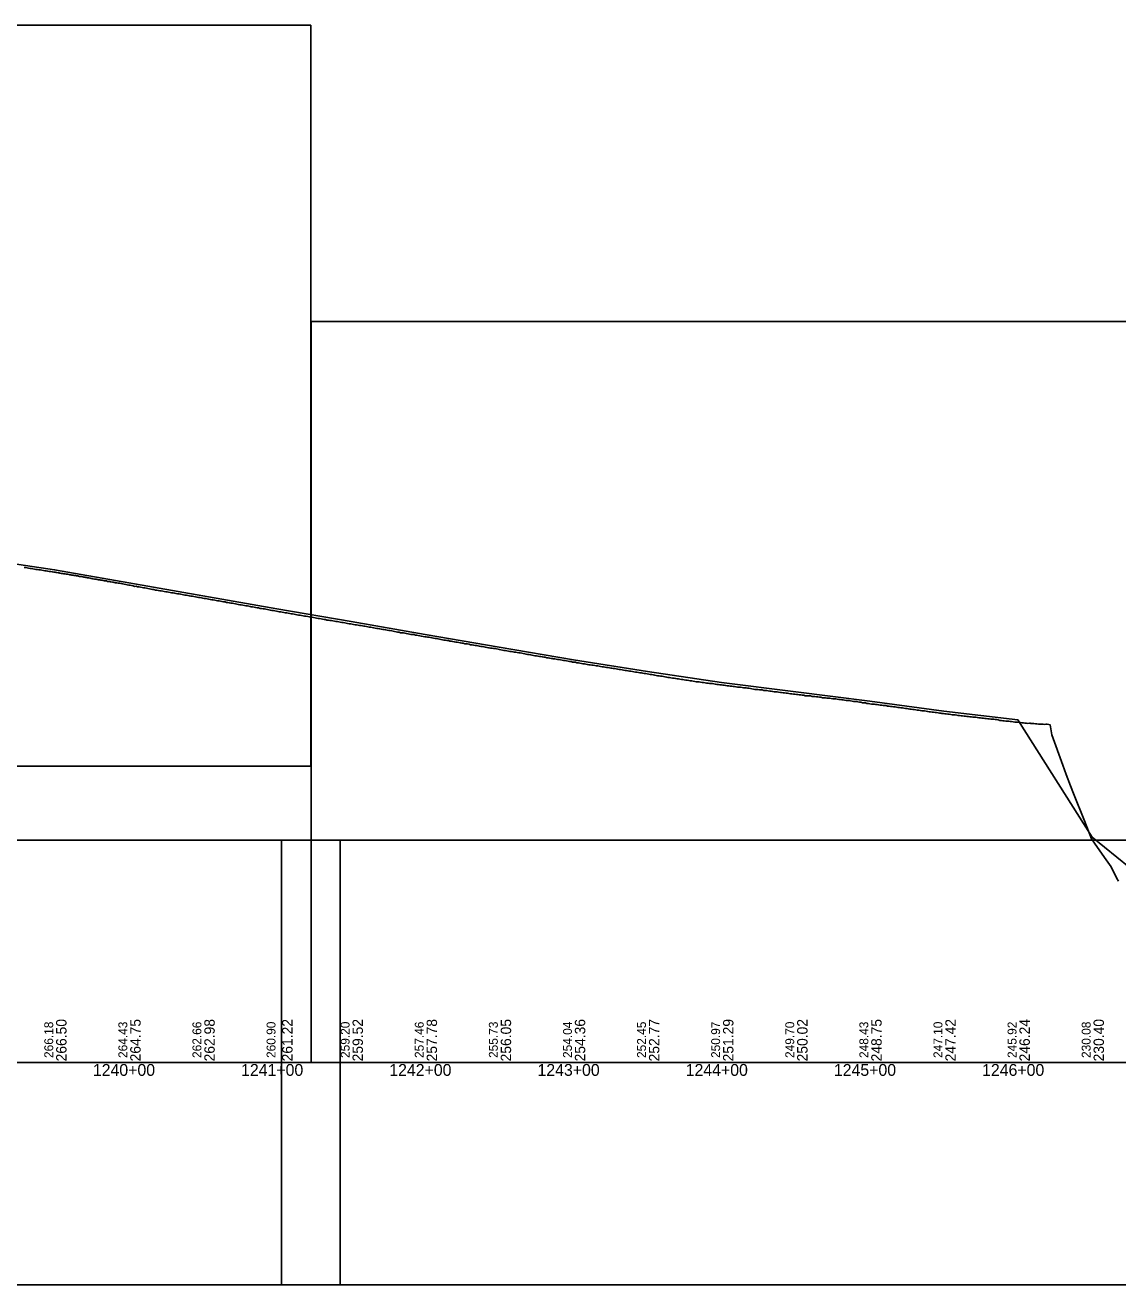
# Model space of a CAD drawing. Extents: x -3627 to 47473, y 2850 to 4350.
# Drawn here: x 11307 to 12045, y 2850 to 3700 of the extents above; entities that cross this region are included whole.
import ezdxf

# ---------------------------------------------------------------- set-up
doc = ezdxf.new("R2010")
doc.units = 0
for name, color, linetype in [('RD_DDB_Profile_EX', 7, 'Continuous'), ('RD_DDB_Profile_PR', 7, 'Continuous'), ('RD_DDB_StaTX', 7, 'Continuous'), ('RD_DDB_StripGrade', 7, 'Continuous'), ('RD_GPK_Profile_Cell', 7, 'Continuous'), ('RD_SHT_ShtClip', 7, 'Continuous')]:
    doc.layers.add(name, color=color, linetype=linetype)

msp = doc.modelspace()

# ---------------------------------------------------------------- linework, layer by layer
at = {"layer": 'RD_DDB_Profile_EX'}
for points in [[(11306.702497, 3334.127615), (11307.703786, 3333.95557), (11308.704824, 3333.8417), (11309.698455, 3333.641885), (11310.701927, 3333.44198), (11311.700801, 3333.30623), (11312.700777, 3333.06418), (11313.701759, 3333.02838), (11314.703124, 3332.79284), (11315.697828, 3332.67114), (11316.697823, 3332.52178), (11317.70129, 3332.421955), (11318.70017, 3332.23674), (11319.70019, 3332.09376), (11320.701094, 3331.908395), (11321.70111, 3331.79419), (11322.697231, 3331.55856), (11323.697271, 3331.42955), (11324.700734, 3331.329625), (11325.699621, 3331.194645), (11326.699688, 3330.96007), (11327.700509, 3330.860125), (11328.398137, 3330.755555), (11328.727924, 3330.695325), (11329.7239, 3330.44505), (11330.421897, 3330.340395), (11330.724297, 3330.234955), (11331.72652, 3330.080035), (11332.424528, 3329.975325), (11333.018039, 3329.940345), (11333.319138, 3329.880155), (11334.016473, 3329.775635), (11334.319858, 3329.73021), (11335.314757, 3329.53994), (11336.013378, 3329.434935), (11336.314595, 3329.45), (11337.015833, 3329.24021), (11337.316486, 3329.19517), (11338.014271, 3329.125525), (11338.316319, 3329.08025), (11339.016724, 3328.94046), (11339.319099, 3328.88011), (11340.011169, 3328.775205), (11340.311938, 3328.7), (11341.310819, 3328.56999), (11342.009598, 3328.43011), (11342.310648, 3328.415075)], [(11342.310648, 3328.415075), (11343.012061, 3328.310105), (11343.312543, 3328.219905), (11344.004769, 3328.080065), (11344.306261, 3328.06501), (11345.308154, 3327.935015), (11346.007394, 3327.76013), (11346.307993, 3327.7), (11347.009857, 3327.59501), (11347.309885, 3327.55), (11348.008282, 3327.4103), (11348.30972, 3327.365095), (11349.005027, 3327.259925), (11349.305482, 3327.17008), (11350.005187, 3327.06501), (11350.305332, 3327.03497), (11351.307221, 3326.854995), (11352.00608, 3326.54031), (11352.307066, 3326.525365), (11353.004508, 3326.45586), (11353.307794, 3326.35), (11354.302664, 3326.219985), (11355.001418, 3326.15), (11355.302523, 3326.11984), (11356.003876, 3325.945085), (11356.304405, 3325.91505), (11357.002307, 3325.7057), (11357.304261, 3325.660485), (11357.999044, 3325.62503), (11358.299989, 3325.594955), (11358.99921, 3325.52517), (11359.299859, 3325.465055), (11360.001669, 3325.36002), (11360.301738, 3325.269945), (11361.000104, 3325.130155), (11361.301604, 3325.0849), (11362.002562, 3325.01505), (11362.303483, 3324.96986), (11362.995274, 3324.690325), (11363.297188, 3324.66013), (11364.299064, 3324.49501), (11364.997899, 3324.42527), (11365.29894, 3324.365075), (11366.297795, 3324.21502), (11366.990607, 3324.11001), (11367.290629, 3324.034975), (11367.993075, 3323.82487), (11368.29337, 3323.76495), (11369.193142, 3323.684985), (11370.194703, 3323.514875), (11371.192429, 3323.385125), (11372.189034, 3323.179475), (11373.186775, 3323.029475), (11374.187253, 3322.8), (11375.28425, 3322.59362), (11376.282005, 3322.320915), (11377.282798, 3322.17889), (11378.276693, 3322.043225), (11379.277501, 3321.828625), (11380.275278, 3321.664315), (11381.277354, 3321.320895), (11382.277735, 3321.36421), (11383.272049, 3321.106195), (11384.269851, 3320.928105), (11385.273311, 3320.763985), (11386.272322, 3320.6), (11387.266653, 3320.427585), (11388.267001, 3320.277645), (11389.267946, 3320.07746), (11390.265778, 3319.80494), (11391.263786, 3319.740695), (11392.261634, 3319.53643), (11393.259481, 3319.204315), (11394.26049, 3319.176975), (11395.260802, 3318.85407), (11396.256321, 3318.75), (11397.254191, 3318.636665), (11398.257666, 3318.40307), (11399.255541, 3318.25), (11400.249921, 3318.136875), (11401.250201, 3317.88946), (11402.252432, 3317.678185), (11403.250329, 3317.56304), (11404.253817, 3317.4), (11405.244981, 3317.22584), (11406.246128, 3317.024335), (11407.245164, 3316.9), (11408.24866, 3316.8), (11409.239809, 3316.50076), (11410.241007, 3316.32521), (11411.241232, 3316.187905), (11412.270572, 3316.06251), (11413.262888, 3315.82503), (11414.263934, 3315.537), (11415.264213, 3315.47492), (11416.265277, 3315.362375), (11417.265549, 3315.174815), (11418.259658, 3314.89904), (11419.314207, 3314.79913), (11420.305281, 3314.61223), (11421.307684, 3314.398795)], [(11421.307684, 3314.398795), (11422.305665, 3314.236635), (11423.309122, 3314.09859), (11424.300189, 3313.84839), (11425.30364, 3313.712035), (11426.301637, 3313.6), (11427.305094, 3313.311985), (11428.303095, 3313.161995), (11429.29858, 3313.023805), (11430.296589, 3312.861915), (11431.300052, 3312.597405), (11432.298064, 3312.485595), (11433.294557, 3312.28522), (11434.29473, 3312.161775), (11435.296045, 3311.985075), (11436.29621, 3311.785175), (11437.28954, 3311.56161), (11438.289698, 3311.461645), (11439.291045, 3311.31156), (11440.291196, 3311.034785), (11441.285537, 3310.911455), (11442.285681, 3310.77297), (11443.287058, 3310.538595), (11444.287195, 3310.32288), (11445.287601, 3310.145545), (11446.280691, 3310.034075), (11447.282098, 3309.91128), (11448.282221, 3309.722625), (11449.280283, 3309.538675), (11450.276694, 3309.283615), (11451.274767, 3308.98976), (11452.278239, 3308.92232), (11453.275344, 3308.7612), (11454.271744, 3308.62216), (11455.382957, 3308.45), (11456.385126, 3308.261085), (11457.384879, 3308.144265), (11458.38774, 3307.922405), (11459.158416, 3307.65), (11459.929866, 3307.561015), (11460.932525, 3307.46098), (11461.931425, 3307.28896), (11462.927222, 3307.15), (11463.930938, 3306.87177), (11464.929843, 3306.72811), (11465.925625, 3306.471695), (11466.928297, 3306.35), (11467.928245, 3306.260845), (11468.924011, 3306.042995), (11469.924807, 3305.82861), (11470.916795, 3305.689305), (11471.919483, 3305.471315), (11472.9232, 3305.181785), (11473.915171, 3305.08178), (11474.917865, 3304.95), (11475.920567, 3304.73948), (11476.912524, 3304.6), (11477.916231, 3304.410455), (11478.911961, 3304.14142), (11479.910879, 3304.08125), (11480.913588, 3303.91038), (11481.909313, 3303.760275), (11482.909217, 3303.52937), (11483.911933, 3303.410275), (11484.90585, 3303.189845), (11485.904761, 3303.06022), (11486.90847, 3302.840625), (11487.904179, 3302.75), (11488.903095, 3302.55), (11489.898791, 3302.3), (11490.901538, 3302.079915), (11491.901412, 3301.93999), (11492.897091, 3301.8), (11493.899845, 3301.690135), (11494.898765, 3301.54007), (11495.89444, 3301.30982), (11496.898134, 3301.15), (11498.084495, 3300.99025), (11499.082949, 3300.790225), (11500.083358, 3300.55), (11501.083772, 3300.44015), (11502.076535, 3300.261185), (11503.076945, 3300.04026), (11504.074824, 3299.76958), (11505.075233, 3299.74017), (11506.076064, 3299.54025), (11507.076465, 3299.430425), (11508.074909, 3299.23038), (11509.075311, 3299.030305), (11510.078107, 3298.8913), (11511.07596, 3298.54017), (11512.076358, 3298.470395), (11513.074786, 3298.3), (11514.077599, 3298.240175), (11515.068024, 3298.07065), (11516.068418, 3297.93036), (11517.068817, 3297.64014), (11518.069075, 3297.53039), (11519.069465, 3297.370475), (11520.067894, 3297.130275), (11521.068284, 3297.0302)], [(11521.068284, 3297.0302), (11522.069147, 3296.880355), (11523.069531, 3296.7), (11524.069918, 3296.44062), (11524.870833, 3296.360215), (11526.070565, 3296.11976), (11527.068981, 3296.030195), (11528.061393, 3295.85), (11528.86275, 3295.649615), (11530.062649, 3295.440165), (11531.063029, 3295.280255), (11532.061447, 3295.180215), (11533.061219, 3294.95995), (11534.0621, 3294.83025), (11535.062473, 3294.65), (11535.863082, 3294.52988), (11536.652242, 3294.36991), (11537.652092, 3294.15), (11538.655829, 3293.91986), (11539.653933, 3293.79005), (11540.652812, 3293.67002), (11541.654813, 3293.529805), (11542.647632, 3293.279725), (11543.645738, 3293.1), (11544.645586, 3292.95), (11545.649322, 3292.8), (11546.647428, 3292.579775), (11547.725313, 3292.45997), (11548.728588, 3292.21982), (11549.728712, 3292.11989), (11550.72806, 3291.910005), (11551.726314, 3291.729955), (11552.728804, 3291.60999), (11553.728931, 3291.429955), (11554.728272, 3291.23992), (11555.719036, 3291.03996), (11556.721522, 3290.82999), (11557.721653, 3290.66988), (11558.719903, 3290.5), (11559.722391, 3290.320045), (11560.72252, 3290.06035), (11561.721859, 3289.980345), (11562.720098, 3289.9), (11563.722584, 3289.6404), (11564.722715, 3289.4), (11565.722048, 3289.31019), (11566.720278, 3289.09084), (11567.723568, 3288.90076), (11568.715444, 3288.81015), (11569.713679, 3288.75), (11570.716163, 3288.480405), (11571.716296, 3288.340675), (11572.715628, 3288.1409), (11573.713853, 3287.990975), (11574.716335, 3287.78979), (11576.009865, 3287.46152), (11577.002754, 3287.35114), (11578.003685, 3287.230535), (11579.007399, 3287.070245), (11579.999286, 3286.93036), (11581.001219, 3286.78014), (11582.000125, 3286.57021), (11583.003839, 3286.38014), (11583.999548, 3286.239815), (11584.997659, 3286.12992), (11586.001373, 3285.86983), (11587.00028, 3285.65997), (11587.996928, 3285.56971), (11588.9941, 3285.24949), (11589.997814, 3285.08936), (11590.993506, 3284.97924), (11591.991634, 3284.81953), (11592.994412, 3284.688925), (11593.994254, 3284.429295), (11594.990866, 3284.3), (11595.991959, 3284.0096), (11596.991788, 3283.959635), (11597.987464, 3283.728615), (11598.987293, 3283.6), (11599.988407, 3283.46905), (11600.999406, 3283.3), (11601.993282, 3282.997275), (11602.996052, 3282.928255), (11603.995902, 3282.640545), (11604.998672, 3282.60942), (11605.99131, 3282.487575), (11606.99408, 3282.28743), (11607.995203, 3281.83723), (11608.987813, 3281.78713), (11609.990596, 3281.686985), (11610.990433, 3281.514975), (11611.993217, 3281.436985), (11612.984945, 3281.155455), (11613.988588, 3280.91837), (11614.989754, 3280.727405), (11615.989577, 3280.62751), (11616.985112, 3280.55), (11617.984083, 3280.27739), (11618.987732, 3280.14093), (11619.98325, 3279.92692), (11620.491182, 3279.8138)], [(11620.491182, 3279.8138), (11621.485517, 3279.705245), (11622.485183, 3279.522975), (11623.485443, 3279.41809), (11624.487798, 3279.29099), (11625.488058, 3279.1), (11626.480621, 3278.891065), (11627.480287, 3278.62697), (11628.483236, 3278.40893), (11629.482902, 3278.28202), (11630.48585, 3278.05893), (11631.477474, 3278), (11632.475392, 3277.767945), (11633.47834, 3277.658915), (11634.478006, 3277.45), (11635.480954, 3277.3), (11636.48062, 3277.15897), (11637.474933, 3276.976615), (11638.473444, 3276.8), (11639.475811, 3276.65886), (11640.476058, 3276.508895), (11641.478425, 3276.35), (11642.470035, 3276.14688), (11643.470289, 3275.9), (11644.470916, 3275.73536), (11645.471163, 3275.541125), (11646.425702, 3275.4), (11647.424086, 3275.258845), (11648.418672, 3275.126075), (11649.417069, 3274.873855), (11650.420344, 3274.682685), (11651.419426, 3274.55), (11652.421093, 3274.441405), (11653.411748, 3274.28289), (11654.410832, 3274.05856), (11655.414116, 3273.91701), (11656.413202, 3273.71702), (11657.414909, 3273.60844), (11658.405557, 3273.458405), (11659.407955, 3273.10832), (11660.407939, 3273.05), (11661.409684, 3272.85829), (11662.408773, 3272.68341), (11663.241396, 3272.55834), (11663.748903, 3272.508235), (11664.742062, 3272.35), (11665.744382, 3272.174375), (11666.742619, 3271.94185), (11667.745755, 3271.858065), (11668.740776, 3271.71588), (11669.740418, 3271.515955), (11670.743565, 3271.342105), (11671.741818, 3271.2), (11672.737609, 3270.97666), (11673.735871, 3270.842195), (11674.739634, 3270.66899), (11675.742809, 3270.561645), (11676.733682, 3270.254165), (11677.73612, 3270.131825), (11678.735139, 3270.05449), (11679.738909, 3269.76987), (11680.730504, 3269.675155), (11681.732966, 3269.39805), (11682.73545, 3269.333775), (11683.728297, 3269.09875), (11684.730786, 3268.984665), (11685.729083, 3268.86985), (11686.732307, 3268.699535), (11687.723139, 3268.442325), (11688.727609, 3268.26466), (11689.730143, 3268.1295), (11690.728453, 3268.079225), (11691.724199, 3267.951385), (11692.722517, 3267.74422), (11693.726294, 3267.63079), (11694.725297, 3267.523725), (11695.735083, 3267.268225), (11696.738749, 3267.0756), (11697.737703, 3266.96823), (11698.741369, 3266.73913), (11699.73146, 3266.652765), (11700.735125, 3266.52991), (11701.73408, 3266.336505), (11702.730059, 3266.1), (11703.212794, 3266.086715), (11704.215852, 3265.9), (11705.215409, 3265.830075), (11706.210078, 3265.65427), (11707.208375, 3265.517125), (11708.211433, 3265.273905), (11709.21145, 3265.123755), (11710.205647, 3264.93707), (11711.208694, 3264.743585), (11712.207014, 3264.587085), (11713.201647, 3264.430955), (11714.201215, 3264.2372), (11715.204263, 3264.17461), (11716.202595, 3264.02444), (11717.197216, 3263.831155), (11718.199829, 3263.587515), (11719.199831, 3263.48744)], [(11719.199831, 3263.48744), (11720.192787, 3263.33765), (11721.192784, 3263.18136), (11722.195402, 3262.969125), (11723.195399, 3262.887575), (11724.18836, 3262.64389), (11725.191411, 3262.5), (11726.190975, 3262.44389), (11727.194026, 3262.251545), (11728.183933, 3262.069795), (11729.186984, 3261.88203), (11730.186548, 3261.78792), (11731.181087, 3261.626275), (11732.18372, 3261.376435), (11733.182557, 3261.18223), (11734.185608, 3261.026515), (11735.176647, 3260.88241), (11736.179689, 3260.738375), (11737.181215, 3260.621175), (11738.172633, 3260.421275), (11739.175279, 3260.215765), (11740.175249, 3260.071275), (11741.176793, 3259.838605), (11742.168193, 3259.72729), (11743.170844, 3259.627445), (11744.257976, 3259.45517), (11745.25965, 3259.311105), (11746.254321, 3259.17822), (11747.25707, 3258.983785), (11748.251699, 3258.83412), (11749.244917, 3258.67926), (11750.186584, 3258.54486), (11751.182493, 3258.37989), (11752.185762, 3258.24003), (11753.181158, 3258.1), (11754.189346, 3257.995265), (11755.184726, 3257.84537), (11756.188035, 3257.627055), (11757.183844, 3257.47763), (11758.179187, 3257.336895), (11759.182516, 3257.195675), (11760.17785, 3256.995785), (11761.181601, 3256.94167), (11762.176205, 3256.78785), (11763.179569, 3256.64199), (11764.175272, 3256.530555), (11765.170566, 3256.388665), (11766.17395, 3256.242535), (11767.169587, 3256.1), (11768.172984, 3255.989295), (11769.168246, 3255.796545), (11770.171991, 3255.73979), (11771.167232, 3255.68684), (11772.170658, 3255.49027), (11773.166192, 3255.290635), (11774.160866, 3255.187985), (11775.164321, 3254.99409), (11776.16413, 3254.93906), (11777.167879, 3254.88928), (11778.16307, 3254.69231), (11779.16657, 3254.54246), (11780.161983, 3254.35), (11781.165496, 3254.29532), (11782.160653, 3254.19556), (11783.155995, 3254.041625), (11784.159529, 3253.9857), (11785.154644, 3253.792315), (11786.158049, 3253.64255), (11787.153162, 3253.44652), (11788.156736, 3253.29494), (11789.151989, 3253.339085), (11790.155577, 3253.190965), (11791.150655, 3253.043095), (11792.145712, 3252.94498), (11792.82433, 3252.842925), (11793.823599, 3252.74382), (11794.826851, 3252.642915), (11795.821132, 3252.543695), (11796.824393, 3252.44303), (11797.814388, 3252.19315), (11798.811602, 3251.94908), (11799.815098, 3251.8), (11800.805443, 3251.797465), (11801.809036, 3251.74528), (11802.812777, 3251.595625), (11803.807857, 3251.44581), (11804.806695, 3251.394775), (11805.810373, 3251.147015), (11806.805347, 3251.04814), (11807.804278, 3250.947395), (11808.807932, 3250.79676), (11809.802975, 3250.698005), (11810.80671, 3250.49835), (11811.80557, 3250.298675), (11812.800558, 3250.2488), (11813.804268, 3250.14857), (11814.803163, 3250.04821), (11815.798135, 3249.94966), (11816.994233, 3249.771255), (11817.805974, 3249.649865), (11818.796227, 3249.549815)], [(11818.796227, 3249.549815), (11819.800405, 3249.499605), (11820.80459, 3249.34936), (11821.794854, 3249.199295), (11822.79903, 3249.049255), (11823.795047, 3248.898995), (11824.799213, 3248.798845), (11825.797665, 3248.64899), (11826.793666, 3248.54848), (11827.797855, 3248.44831), (11828.796282, 3248.348645), (11829.792316, 3248.198515), (11830.796442, 3248.04838), (11831.794906, 3247.848725), (11832.790946, 3247.798465), (11833.795092, 3247.549175), (11834.36085, 3247.54765), (11835.357229, 3247.497645), (11836.353668, 3247.397345), (11837.357961, 3247.34641), (11838.354411, 3247.09735), (11839.358694, 3246.997235), (11840.355153, 3246.946475), (11841.361477, 3246.845825), (11842.358115, 3246.74548), (11843.342564, 3246.54757), (11844.365169, 3246.49602), (11845.347652, 3246.2), (11846.366163, 3246.147105), (11847.347437, 3246.04847), (11848.367037, 3245.94529), (11849.363708, 3245.89338), (11850.342922, 3245.84391), (11851.346976, 3245.646445), (11852.36126, 3245.495345), (11853.346619, 3245.39715), (11854.342365, 3245.345045), (11855.366538, 3245.14495), (11856.347474, 3244.997825), (11857.373629, 3244.89225), (11858.37035, 3244.793105), (11859.343165, 3244.64643), (11860.371172, 3244.49637), (11861.342779, 3244.39875), (11862.372179, 3244.29746), (11863.368721, 3244.196065), (11864.346432, 3244.05), (11865.369733, 3243.895885), (11866.338123, 3243.701415), (11867.370524, 3243.647135), (11868.343031, 3243.55), (11869.347083, 3243.348475), (11870.34286, 3243.203135), (11871.378522, 3243.148415), (11872.342602, 3242.7614), (11873.338387, 3242.758345), (11874.342441, 3242.708435), (11875.372662, 3242.308645), (11876.377085, 3242.348255), (11877.337981, 3242.155365), (11878.378105, 3241.86806), (11879.38063, 3241.866955), (11880.338809, 3241.86732), (11881.366232, 3241.5711), (11882.37043, 3241.56743), (11883.374308, 3241.37152), (11884.365105, 3241.223545), (11885.368981, 3241.071795), (11886.372947, 3240.971985), (11887.369296, 3240.92244), (11888.367626, 3240.82024), (11889.371823, 3240.56634), (11890.367843, 3240.46251), (11891.36627, 3240.318595), (11892.370467, 3240.17502), (11893.366487, 3240.025525), (11894.370684, 3239.9236), (11895.369009, 3239.7713), (11896.365132, 3239.619525), (11897.369329, 3239.517505), (11898.359833, 3239.41756), (11899.364032, 3239.315495), (11900.367866, 3239.120095), (11901.363993, 3238.970455), (11902.362681, 3238.91579), (11903.366508, 3238.672755), (11904.362905, 3238.475485), (11905.366722, 3238.371025), (11906.365151, 3238.266225), (11907.361555, 3238.17123), (11908.365365, 3238.023785), (11909.364066, 3237.82362), (11910.360089, 3237.719235), (11911.364008, 3237.61937), (11912.367804, 3237.419525), (11913.358736, 3237.372025), (11914.362934, 3237.26726), (11915.358957, 3237.120065), (11916.357384, 3236.972405), (11917.361172, 3236.7276), (11918.357605, 3236.675505)], [(11918.357605, 3236.675505), (11919.376738, 3236.5308), (11920.375363, 3236.3255), (11921.371743, 3236.18107), (11922.37574, 3236.17345), (11923.374369, 3235.981075), (11924.370752, 3235.78417), (11925.374744, 3235.72645), (11925.971078, 3235.63158), (11926.966969, 3235.529375), (11927.96581, 3235.38185), (11928.969593, 3235.274035), (11929.96814, 3235.126525), (11930.971476, 3235.03471), (11931.96766, 3234.882535), (11932.966209, 3234.72962), (11933.969984, 3234.67709), (11934.968833, 3234.582315), (11935.964725, 3234.34371), (11936.963273, 3234.10156), (11937.967047, 3234.09641), (11938.97112, 3233.99947), (11939.96967, 3233.88276), (11940.965563, 3233.7443), (11941.964112, 3233.64951), (11942.968186, 3233.45261), (11943.966735, 3233.446765), (11944.970504, 3233.24704), (11945.961486, 3233.188825), (11946.965255, 3233.047425), (11947.96902, 3233.04209), (11948.967105, 3232.98347), (11949.963307, 3232.792445), (11950.961857, 3232.694985), (11951.965618, 3232.645245), (11952.96417, 3232.40338), (11953.968241, 3232.33959), (11954.964135, 3232.23726), (11955.962686, 3232.18418), (11956.966759, 3232.034395), (11957.96531, 3231.889875), (11958.969066, 3231.74583), (11959.959757, 3231.6959), (11960.96383, 3231.643305), (11961.962381, 3231.54303), (11962.966135, 3231.431735), (11963.962031, 3231.282145), (11965.054879, 3230.85863), (11966.112042, 3230.705265), (11967.049786, 3230.658915), (11968.053504, 3230.562145), (11969.057219, 3230.412435), (11970.048418, 3230.31244), (11971.052134, 3230.256745), (11972.115642, 3230.15988), (11973.051684, 3230.019605), (11974.050264, 3229.869035), (11975.114543, 3229.76917), (11976.050319, 3229.722955), (11977.048897, 3229.619345), (11978.280805, 3229.543715), (11979.048447, 3229.46712), (11980.052665, 3229.320235), (11981.051242, 3229.222585), (11982.046751, 3229.076205), (11983.050458, 3228.920205), (11984.054164, 3228.873355), (11985.044878, 3228.91708), (11985.598014, 3228.88961), (11986.049096, 3228.87319), (11987.052804, 3228.71708), (11988.056512, 3228.67012), (11989.047226, 3228.57288), (11990.050936, 3228.52287), (11991.115713, 3228.38187), (11992.050995, 3228.3825), (11993.049576, 3228.32553), (11994.113482, 3228.37836), (11995.049131, 3228.14402), (11996.053352, 3228.24382), (11997.111568, 3228.32166), (11998.107797, 3228.192215), (11999.092864, 3227.84066), (12000.232434, 3221.21318), (12007.549644, 3200.72147), (12009.852719, 3194.2719), (12012.74671, 3186.77351), (12014.866853, 3181.44025), (12022.184063, 3163.032595), (12027.023819, 3150.856695), (12029.501273, 3147.291335), (12036.818483, 3136.760165), (12040.159552, 3131.95123), (12044.135692, 3124.158525), (12045.05235, 3122.38407)]]:
    msp.add_lwpolyline(points, dxfattribs=at)
at = {"layer": 'RD_DDB_Profile_PR'}
msp.add_lwpolyline([(11277.33, 3339.935), (11327.33, 3332.497), (11377.33, 3323.7725), (11427.33, 3314.908), (11477.33, 3306.121), (11527.33, 3297.583), (11577.33, 3288.9115), (11627.33, 3280.2665), (11677.33, 3271.7815), (11727.33, 3263.8265), (11777.33, 3256.457), (11827.33, 3250.095), (11877.33, 3243.757), (11927.33, 3237.076), (11977.33, 3231.202), (12027.33, 3152.016), (12077.33, 3111.495)], dxfattribs=at)
at = {"layer": 'RD_GPK_Profile_Cell'}
msp.add_line((1000, 3000), (46705.077602, 3000), dxfattribs=at)
at = {"layer": 'RD_SHT_ShtClip'}
for points in [[(11500.165, 3200), (11500.165, 3700), (11500.165, 3700), (10000.33, 3700), (10000.33, 3200)], [(13000.165, 3000), (13000.165, 3500), (13000.165, 3500), (11500.33, 3500), (11500.33, 3000)], [(9980.33, 3150), (11520, 3150), (11520, 2850), (9980.33, 2850)], [(11480.33, 3150), (13020, 3150), (13020, 2850), (11480.33, 2850)]]:
    msp.add_lwpolyline(points, close=True, dxfattribs=at)

# ---------------------------------------------------------------- texts
at = {"layer": 'RD_DDB_StaTX'}
for s, p in [('1240+00', (11353.125471, 2991)), ('1241+00', (11453.125471, 2991)), ('1242+00', (11553.125471, 2991)), ('1243+00', (11653.125471, 2991)), ('1244+00', (11753.125471, 2991)), ('1245+00', (11853.125471, 2991)), ('1246+00', (11953.125471, 2991))]:
    msp.add_text(s, height=8, dxfattribs=at).set_placement(p)
at = {"layer": 'RD_DDB_StripGrade'}
for s, height, p in [('266.18', 6, (11326.33, 3003.073688)), ('266.50', 7, (11335.33, 3000.75)), ('264.43', 6, (11376.33, 3003.073688)), ('264.75', 7, (11385.33, 3000.75)), ('262.66', 6, (11426.33, 3003.073688)), ('262.98', 7, (11435.33, 3000.75)), ('260.90', 6, (11476.33, 3003.073688)), ('261.22', 7, (11487.836884, 3000.75)), ('259.20', 6, (11526.33, 3003.073688)), ('259.52', 7, (11535.33, 3000.75)), ('257.46', 6, (11576.33, 3003.073688)), ('257.78', 7, (11585.33, 3000.75)), ('255.73', 6, (11626.33, 3003.073688)), ('256.05', 7, (11635.33, 3000.75)), ('254.04', 6, (11676.33, 3003.073688)), ('254.36', 7, (11685.33, 3000.75)), ('252.45', 6, (11726.33, 3003.073688)), ('252.77', 7, (11735.33, 3000.75)), ('250.97', 6, (11776.33, 3003.073688)), ('251.29', 7, (11785.33, 3000.75)), ('249.70', 6, (11826.33, 3003.073688)), ('250.02', 7, (11835.33, 3000.75)), ('248.43', 6, (11876.33, 3003.073688)), ('248.75', 7, (11885.33, 3000.75)), ('247.10', 6, (11926.33, 3003.073688)), ('247.42', 7, (11935.33, 3000.75)), ('245.92', 6, (11976.33, 3003.073688)), ('246.24', 7, (11985.33, 3000.75)), ('230.08', 6, (12026.33, 3003.073688)), ('230.40', 7, (12035.33, 3000.75))]:
    msp.add_text(s, height=height, rotation=90, dxfattribs=at).set_placement(p)

doc.saveas('drawing.dxf')
